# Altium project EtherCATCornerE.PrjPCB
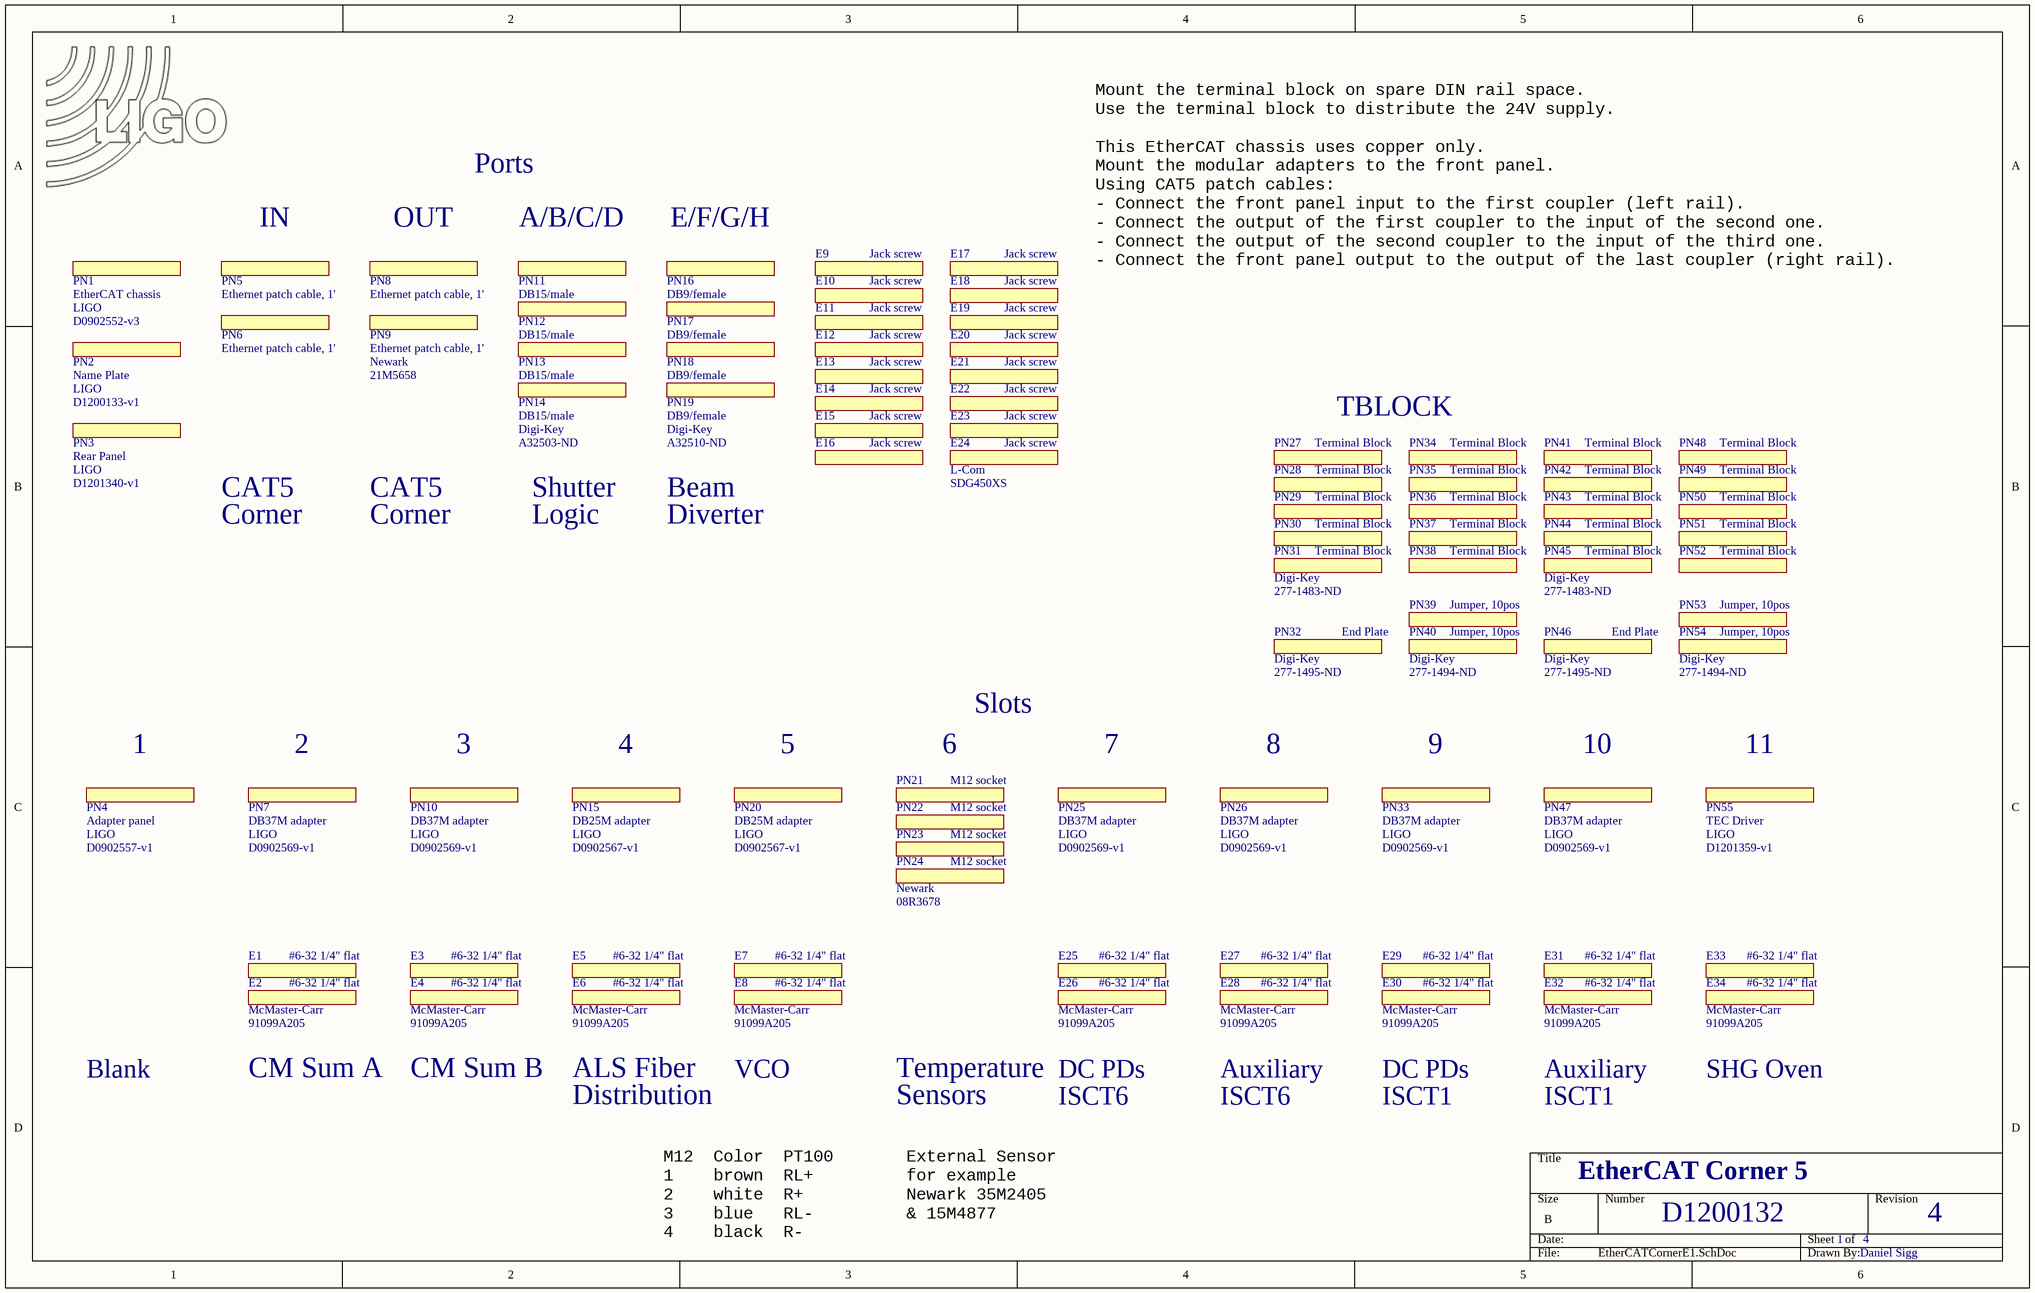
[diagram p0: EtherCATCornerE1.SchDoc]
Title: D1200132
4 sheets, 167 parts. Net scope: global (net labels, ports and power ports of the same name join across sheets).
Sheets:
  EtherCATCornerE1.SchDoc
  EtherCATCornerE2.SchDoc
  EtherCATCornerE3.SchDoc
  EtherCATCornerE4.SchDoc

## Sheet EtherCATCornerE1.SchDoc: D1200132
size B; Engineer: Daniel Sigg; Revision: 3; PageSetup: Record=PageOptions¦CenterHorizontal=True¦CenterVertical=True¦PrintScale=1.12¦XCorrection=1.00¦YCorrection=1.00¦PrintKind=0¦BorderSize=5000000¦LeftOffset=0¦BottomOffset=0¦Orientation=2¦PaperLength=1000¦PaperWidth=1000¦Scale=100¦PaperSource=7¦PrintQuality=-4¦MediaType=1¦DitherType=10¦PaperKind=11 x 17¦PrintScaleMode=1

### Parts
E1  #6-32 1/4" flat  (mechanical)
E2  #6-32 1/4" flat  Part Number: 91099A205  Distributor: McMaster-Carr  (mechanical)
E3  #6-32 1/4" flat  (mechanical)
E4  #6-32 1/4" flat  Part Number: 91099A205  Distributor: McMaster-Carr  (mechanical)
E5  #6-32 1/4" flat  (mechanical)
E6  #6-32 1/4" flat  Part Number: 91099A205  Distributor: McMaster-Carr  (mechanical)
E7  #6-32 1/4" flat  (mechanical)
E8  #6-32 1/4" flat  Part Number: 91099A205  Distributor: McMaster-Carr  (mechanical)
E9  Jack screw  (mechanical)
E10  Jack screw  (mechanical)
E11  Jack screw  (mechanical)
E12  Jack screw  (mechanical)
E13  Jack screw  (mechanical)
E14  Jack screw  (mechanical)
E15  Jack screw  (mechanical)
E16  Jack screw  (mechanical)
E17  Jack screw  (mechanical)
E18  Jack screw  (mechanical)
E19  Jack screw  (mechanical)
E20  Jack screw  (mechanical)
E21  Jack screw  (mechanical)
E22  Jack screw  (mechanical)
E23  Jack screw  (mechanical)
E24  Jack screw  Part Number: SDG450XS  Distributor: L-Com  (mechanical)
E25  #6-32 1/4" flat  (mechanical)
E26  #6-32 1/4" flat  Part Number: 91099A205  Distributor: McMaster-Carr  (mechanical)
E27  #6-32 1/4" flat  (mechanical)
E28  #6-32 1/4" flat  Part Number: 91099A205  Distributor: McMaster-Carr  (mechanical)
E29  #6-32 1/4" flat  (mechanical)
E30  #6-32 1/4" flat  Part Number: 91099A205  Distributor: McMaster-Carr  (mechanical)
E31  #6-32 1/4" flat  (mechanical)
E32  #6-32 1/4" flat  Part Number: 91099A205  Distributor: McMaster-Carr  (mechanical)
E33  #6-32 1/4" flat  (mechanical)
E34  #6-32 1/4" flat  Part Number: 91099A205  Distributor: McMaster-Carr  (mechanical)
LOGO?  LIGO logo  [LIGO_LOGO]  (value not drawn)  (graphical)
PN1  EtherCAT chassis  Part Number: D0902552-v3  Distributor: LIGO  (mechanical)
PN2  Name Plate  Part Number: D1200133-v1  Distributor: LIGO  (mechanical)
PN3  Rear Panel  Part Number: D1201340-v1  Distributor: LIGO  (mechanical)
PN4  Adapter panel  Part Number: D0902557-v1  Distributor: LIGO  (mechanical)
PN5  Ethernet patch cable, 1'  (mechanical)
PN6  Ethernet patch cable, 1'  (mechanical)
PN7  DB37M adapter  Part Number: D0902569-v1  Distributor: LIGO  (mechanical)
PN8  Ethernet patch cable, 1'  (mechanical)
PN9  Ethernet patch cable, 1'  Part Number: 21M5658  Distributor: Newark  (mechanical)
PN10  DB37M adapter  Part Number: D0902569-v1  Distributor: LIGO  (mechanical)
PN11  DB15/male  (mechanical)
PN12  DB15/male  (mechanical)
PN13  DB15/male  (mechanical)
PN14  DB15/male  Part Number: A32503-ND  Distributor: Digi-Key  (mechanical)
PN15  DB25M adapter  Part Number: D0902567-v1  Distributor: LIGO  (mechanical)
PN16  DB9/female  (mechanical)
PN17  DB9/female  (mechanical)
PN18  DB9/female  (mechanical)
PN19  DB9/female  Part Number: A32510-ND  Distributor: Digi-Key  (mechanical)
PN20  DB25M adapter  Part Number: D0902567-v1  Distributor: LIGO  (mechanical)
PN21  M12 socket  (mechanical)
PN22  M12 socket  (mechanical)
PN23  M12 socket  (mechanical)
PN24  M12 socket  Part Number: 08R3678  Distributor: Newark  (mechanical)
PN25  DB37M adapter  Part Number: D0902569-v1  Distributor: LIGO  (mechanical)
PN26  DB37M adapter  Part Number: D0902569-v1  Distributor: LIGO  (mechanical)
PN27  Terminal Block  (mechanical)
PN28  Terminal Block  (mechanical)
PN29  Terminal Block  (mechanical)
PN30  Terminal Block  (mechanical)
PN31  Terminal Block  Part Number: 277-1483-ND  Distributor: Digi-Key  (mechanical)
PN32  End Plate  Part Number: 277-1495-ND  Distributor: Digi-Key  (mechanical)
PN33  DB37M adapter  Part Number: D0902569-v1  Distributor: LIGO  (mechanical)
PN34  Terminal Block  (mechanical)
PN35  Terminal Block  (mechanical)
PN36  Terminal Block  (mechanical)
PN37  Terminal Block  (mechanical)
PN38  Terminal Block  (mechanical)
PN39  Jumper, 10pos  (mechanical)
PN40  Jumper, 10pos  Part Number: 277-1494-ND  Distributor: Digi-Key  (mechanical)
PN41  Terminal Block  (mechanical)
PN42  Terminal Block  (mechanical)
PN43  Terminal Block  (mechanical)
PN44  Terminal Block  (mechanical)
PN45  Terminal Block  Part Number: 277-1483-ND  Distributor: Digi-Key  (mechanical)
PN46  End Plate  Part Number: 277-1495-ND  Distributor: Digi-Key  (mechanical)
PN47  DB37M adapter  Part Number: D0902569-v1  Distributor: LIGO  (mechanical)
PN48  Terminal Block  (mechanical)
PN49  Terminal Block  (mechanical)
PN50  Terminal Block  (mechanical)
PN51  Terminal Block  (mechanical)
PN52  Terminal Block  (mechanical)
PN53  Jumper, 10pos  (mechanical)
PN54  Jumper, 10pos  Part Number: 277-1494-ND  Distributor: Digi-Key  (mechanical)
PN55  TEC Driver  Part Number: D1201359-v1  Distributor: LIGO  (mechanical)

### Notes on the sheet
- (near PN5) IN
- (near PN8) OUT
- Ports
- (near PN11) A/B/C/D
- (near PN16) E/F/G/H
- Mount the terminal block on spare DIN rail space.
  Use the terminal block to distribute the 24V supply.
  This EtherCAT chassis uses copper only.
  Mount the modular adapters to the front panel.
  Using CAT5 patch cables:
  - Connect the front panel input to the first coupler (left rail).
  - Connect the output of the first coupler to the input of the second one.
  - Connect the output of the second coupler to the input of the third one.
  - Connect the front panel output to the output of the last coupler (right rail).
- (near PN34) TBLOCK
- CAT5
- Shutter
- Beam
- Corner
- Logic
- Diverter
- (near PN4) 1
- (near PN7) 2
- (near PN10) 3
- (near PN15) 4
- (near PN20) 5
- 6
- Slots
- (near PN25) 7
- (near PN26) 8
- (near PN33) 9
- (near PN47) 10
- (near PN55) 11
- Blank
- CM Sum A
- CM Sum B
- ALS Fiber
- Distribution
- VCO
- Temperature
- Sensors
- DC PDs
- ISCT6
- Auxiliary
- ISCT1
- SHG Oven
- EtherCAT Corner 5
- M12  Color  PT100
  1    brown  RL+
  2    white  R+
  3    blue   RL-
  4    black  R-
- External Sensor
  for example
  Newark 35M2405
  & 15M4877
- D1200132
- 1
- 4
- Daniel Sigg

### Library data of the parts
E1 E3 E5 E7 E25 E27 E29 E31 E33 = Partlist: #6-32 1/4" flat head screw; Part Number: 91099A205
E2 E4 E6 E8 E26 E28 E30 E32 E34 = Partlist: #6-32 1/4" flat head screw
E9-E23 = Partlist: Jack screw, 45 inch thread; Part Number: SDG450XS
E24 = Partlist: Jack screw, 45 inch thread
LOGO? = LIGO_logo
PN1-PN3 PN7 PN9 PN10 PN14 PN15 PN19 PN20 PN24-PN26 PN33 PN47 = Partlist: Additional part number
PN4 = Partlist: Blank
PN5 PN6 PN8 = Partlist: Additional part number; Part Number: 21M5658
PN11-PN13 = Partlist: Additional part number; Part Number: A32503-ND
PN16-PN18 = Partlist: Additional part number; Part Number: A32510-ND
PN21-PN23 = Partlist: Additional part number; Part Number: 08R3678
PN27-PN30 PN34-PN38 PN41-PN44 PN48-PN52 = Partlist: Part Number: 277-1483-ND
PN31 PN32 PN40 PN45 PN46 PN54 = Partlist
PN39 PN53 = Partlist: Part Number: 277-1494-ND
PN55 = Partlist: TEC Driver PCB

## Sheet EtherCATCornerE2.SchDoc: D1200132
size B
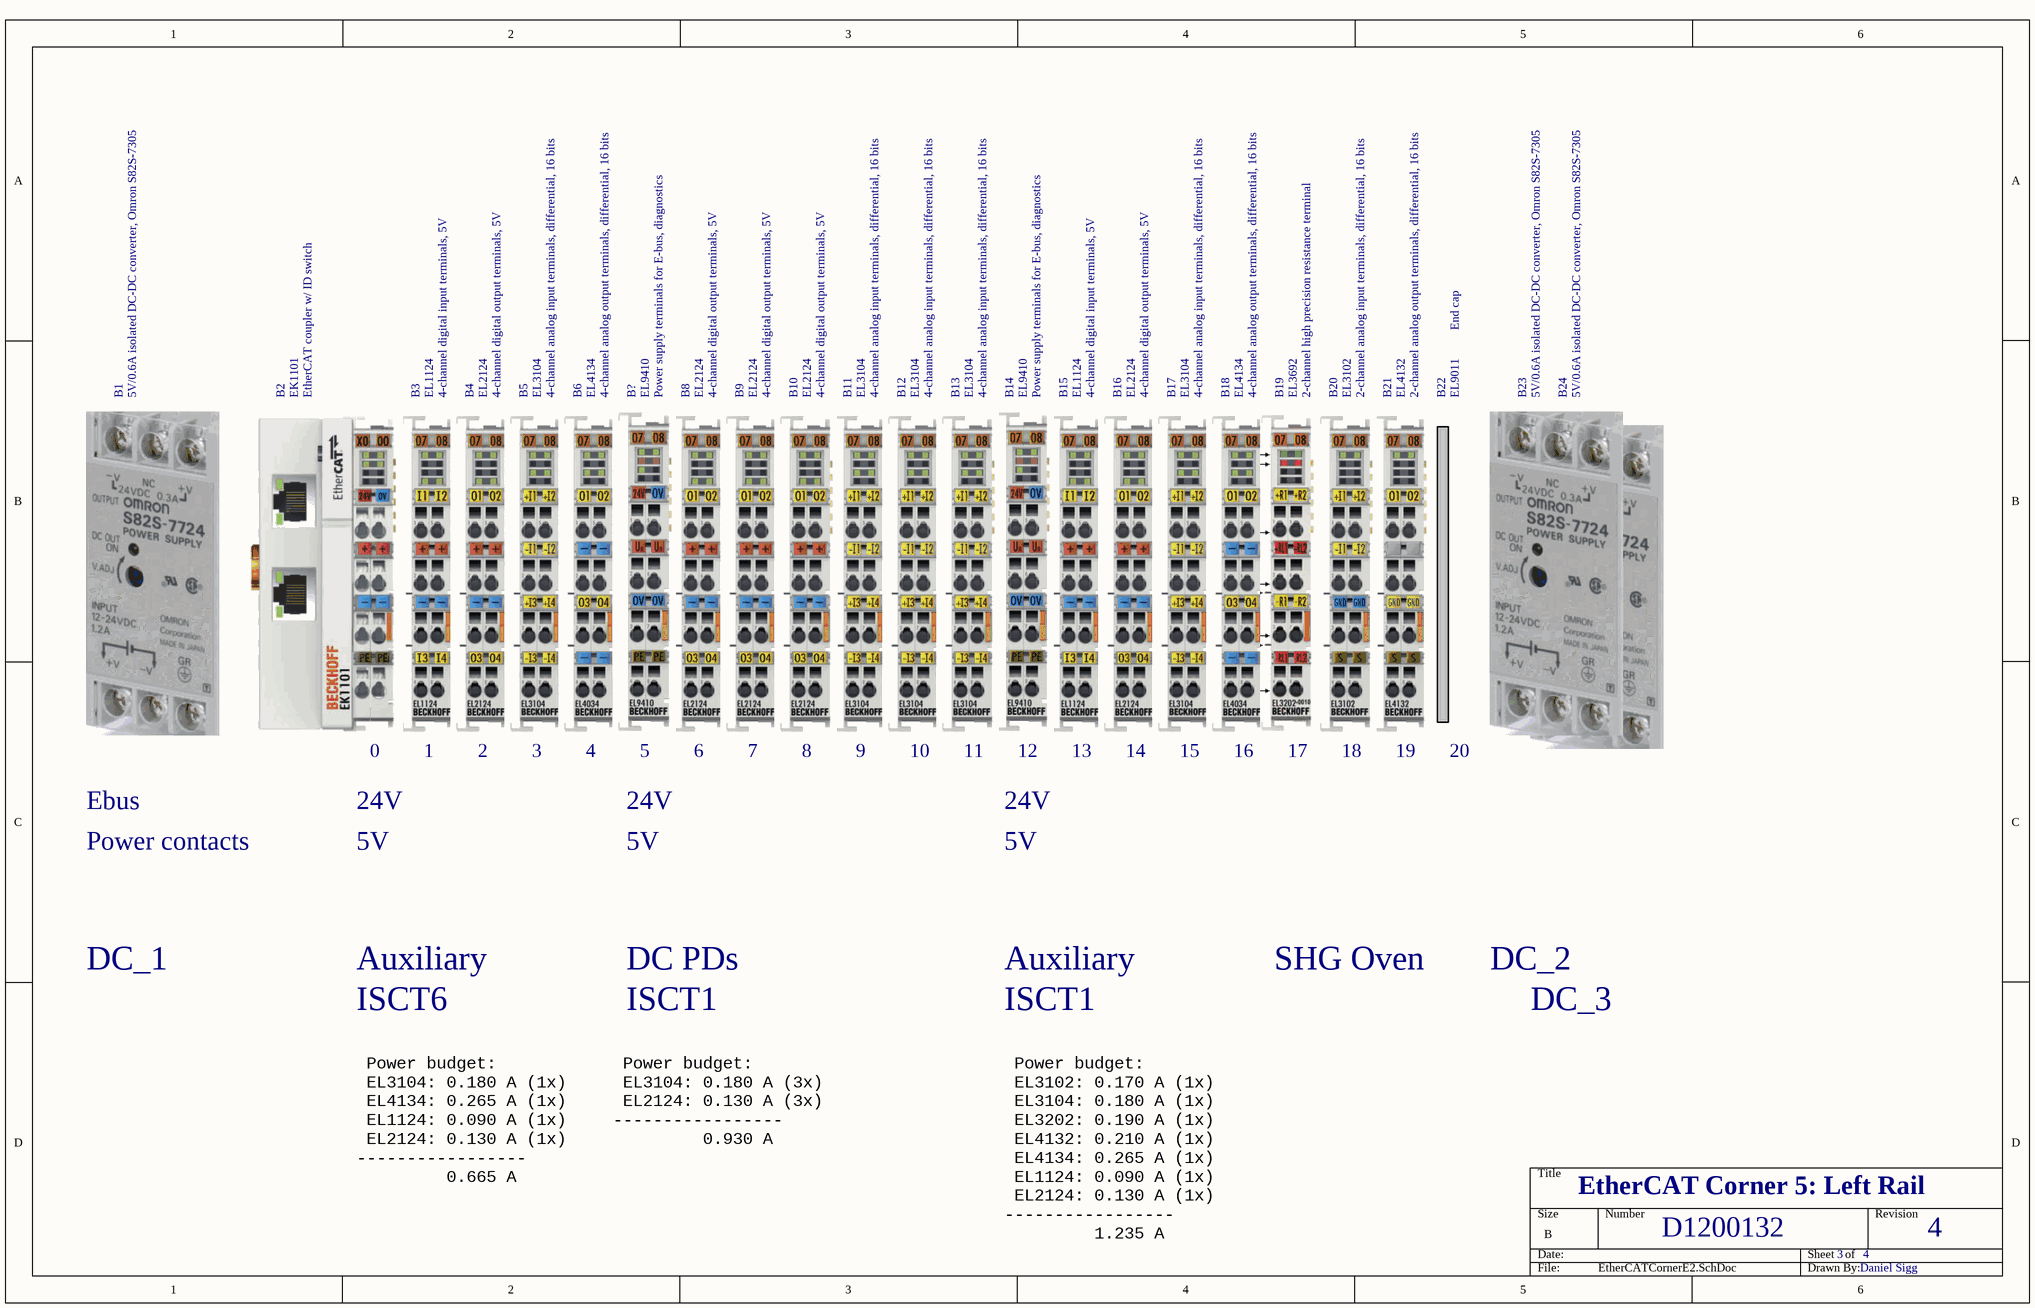
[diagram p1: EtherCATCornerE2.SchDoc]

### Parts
B1  5V/0.6A isolated DC-DC converter, Omron S82S-7305
B2  EtherCAT coupler w/ ID switch
B3  4-channel digital input terminals, 5V
B4  4-channel digital output terminals, 5V
B5  4-channel analog input terminals, differential, 16 bits
B6  4-channel analog output terminals, differential, 16 bits
B8  4-channel digital output terminals, 5V
B9  4-channel digital output terminals, 5V
B10  4-channel digital output terminals, 5V
B11  4-channel analog input terminals, differential, 16 bits
B12  4-channel analog input terminals, differential, 16 bits
B13  4-channel analog input terminals, differential, 16 bits
B14  Power supply terminals for E-bus, diagnostics
B15  4-channel digital input terminals, 5V
B16  4-channel digital output terminals, 5V
B17  4-channel analog input terminals, differential, 16 bits
B18  4-channel analog output terminals, differential, 16 bits
B19  2-channel high precision resistance terminal  Part Number: EL3692
B20  2-channel analog input terminals, differential, 16 bits
B21  2-channel analog output terminals, differential, 16 bits
B22  End cap
B23  5V/0.6A isolated DC-DC converter, Omron S82S-7305
B24  5V/0.6A isolated DC-DC converter, Omron S82S-7305
B?  Power supply terminals for E-bus, diagnostics

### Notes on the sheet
- (near B3) 0
- 1
- 2
- 3
- 4
- 5
- 6
- 7
- 8
- 9
- (near B13) 10
- (near B14) 11
- (near B15) 12
- (near B16) 13
- (near B17) 14
- (near B18) 15
- (near B19) 16
- (near B20) 17
- (near B21) 18
- (near B22) 19
- 20
- (near B1) Ebus
- Power contacts
- 24V
- 5V
- DC_1
- Auxiliary
- DC PDs
- SHG Oven
- DC_2
- ISCT6
- ISCT1
- DC_3
- EtherCAT Corner 5: Left Rail
- Power budget:
  EL3104: 0.180 A (1x)
  EL4134: 0.265 A (1x)
  EL1124: 0.090 A (1x)
  EL2124: 0.130 A (1x)
  -----------------
  0.665 A
- Power budget:
  EL3104: 0.180 A (3x)
  EL2124: 0.130 A (3x)
  -----------------
  0.930 A
- Power budget:
  EL3102: 0.170 A (1x)
  EL3104: 0.180 A (1x)
  EL3202: 0.190 A (1x)
  EL4132: 0.210 A (1x)
  EL4134: 0.265 A (1x)
  EL1124: 0.090 A (1x)
  EL2124: 0.130 A (1x)
  -----------------
  1.235 A
- D1200132
- Daniel Sigg

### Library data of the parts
B1 B23 B24 = S82S-7305: Part Number: 27C5226
B2 = EK1101: Beckhoff EtherCAT coupler w/ ID switch
B3 B15 = EL1124
B4 B8-B10 B16 = EL2124
B5 B11-B13 B17 = EL3104
B6 B18 = EL4134
B14 B? = EL9410
B19 = EL3202-0010: 2-channel high precision input terminal PT100 (RTD) for 2- or 3-wire connection
B20 = EL3102
B21 = EL4132
B22 = EL9011

## Sheet EtherCATCornerE3.SchDoc: D1200132
size B
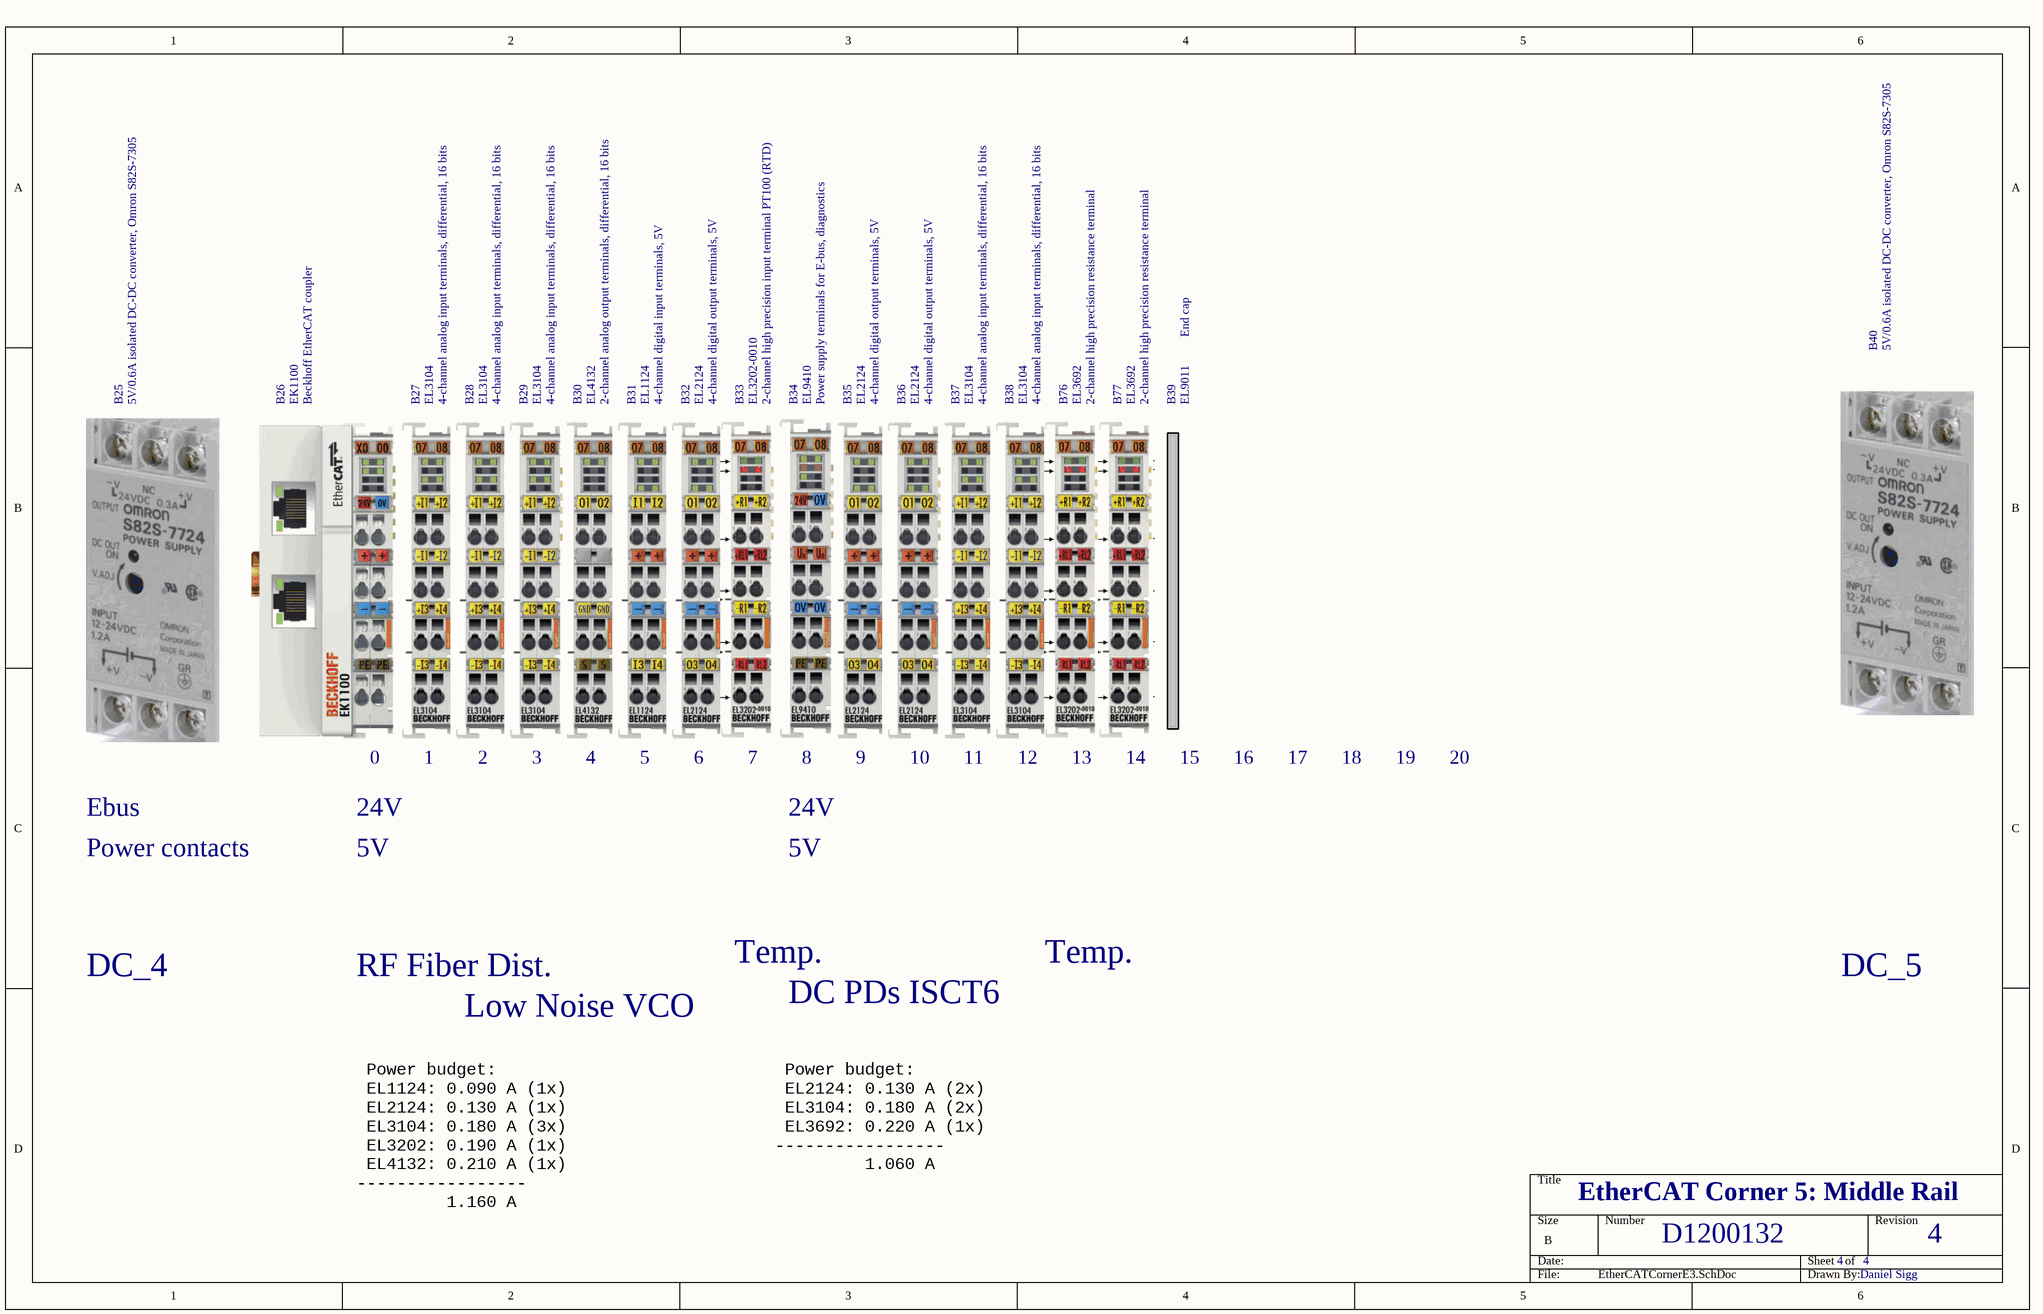
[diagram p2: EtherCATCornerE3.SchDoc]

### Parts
B25  5V/0.6A isolated DC-DC converter, Omron S82S-7305
B26  Beckhoff EtherCAT coupler
B27  4-channel analog input terminals, differential, 16 bits
B28  4-channel analog input terminals, differential, 16 bits
B29  4-channel analog input terminals, differential, 16 bits
B30  2-channel analog output terminals, differential, 16 bits
B31  4-channel digital input terminals, 5V
B32  4-channel digital output terminals, 5V
B33  2-channel high precision input terminal PT100 (RTD)
B34  Power supply terminals for E-bus, diagnostics
B35  4-channel digital output terminals, 5V
B36  4-channel digital output terminals, 5V
B37  4-channel analog input terminals, differential, 16 bits
B38  4-channel analog input terminals, differential, 16 bits
B39  End cap
B40  5V/0.6A isolated DC-DC converter, Omron S82S-7305
B76  2-channel high precision resistance terminal  Part Number: EL3692
B77  2-channel high precision resistance terminal  Part Number: EL3692

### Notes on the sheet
- (near B27) 0
- 1
- 2
- 3
- 4
- 5
- 6
- 7
- 8
- 9
- (near B37) 10
- (near B38) 11
- (near B76) 12
- (near B77) 13
- (near B39) 14
- (near B39) 15
- 16
- 17
- 18
- 19
- 20
- (near B25) Ebus
- Power contacts
- 24V
- 5V
- DC_4
- RF Fiber Dist.
- Temp.
- DC_5
- Low Noise VCO
- DC PDs ISCT6
- EtherCAT Corner 5: Middle Rail
- Power budget:
  EL1124: 0.090 A (1x)
  EL2124: 0.130 A (1x)
  EL3104: 0.180 A (3x)
  EL3202: 0.190 A (1x)
  EL4132: 0.210 A (1x)
  -----------------
  1.160 A
- Power budget:
  EL2124: 0.130 A (2x)
  EL3104: 0.180 A (2x)
  EL3692: 0.220 A (1x)
  -----------------
  1.060 A
- D1200132
- Daniel Sigg

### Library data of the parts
B25 B40 = S82S-7305: Part Number: 27C5226
B26 = EK1100
B27-B29 B37 B38 = EL3104
B30 = EL4132
B31 = EL1124
B32 B35 B36 = EL2124
B33 B76 B77 = EL3202-0010: as B19 on sheet EtherCATCornerE2
B34 = EL9410
B39 = EL9011

## Sheet EtherCATCornerE4.SchDoc: D1200132
size B
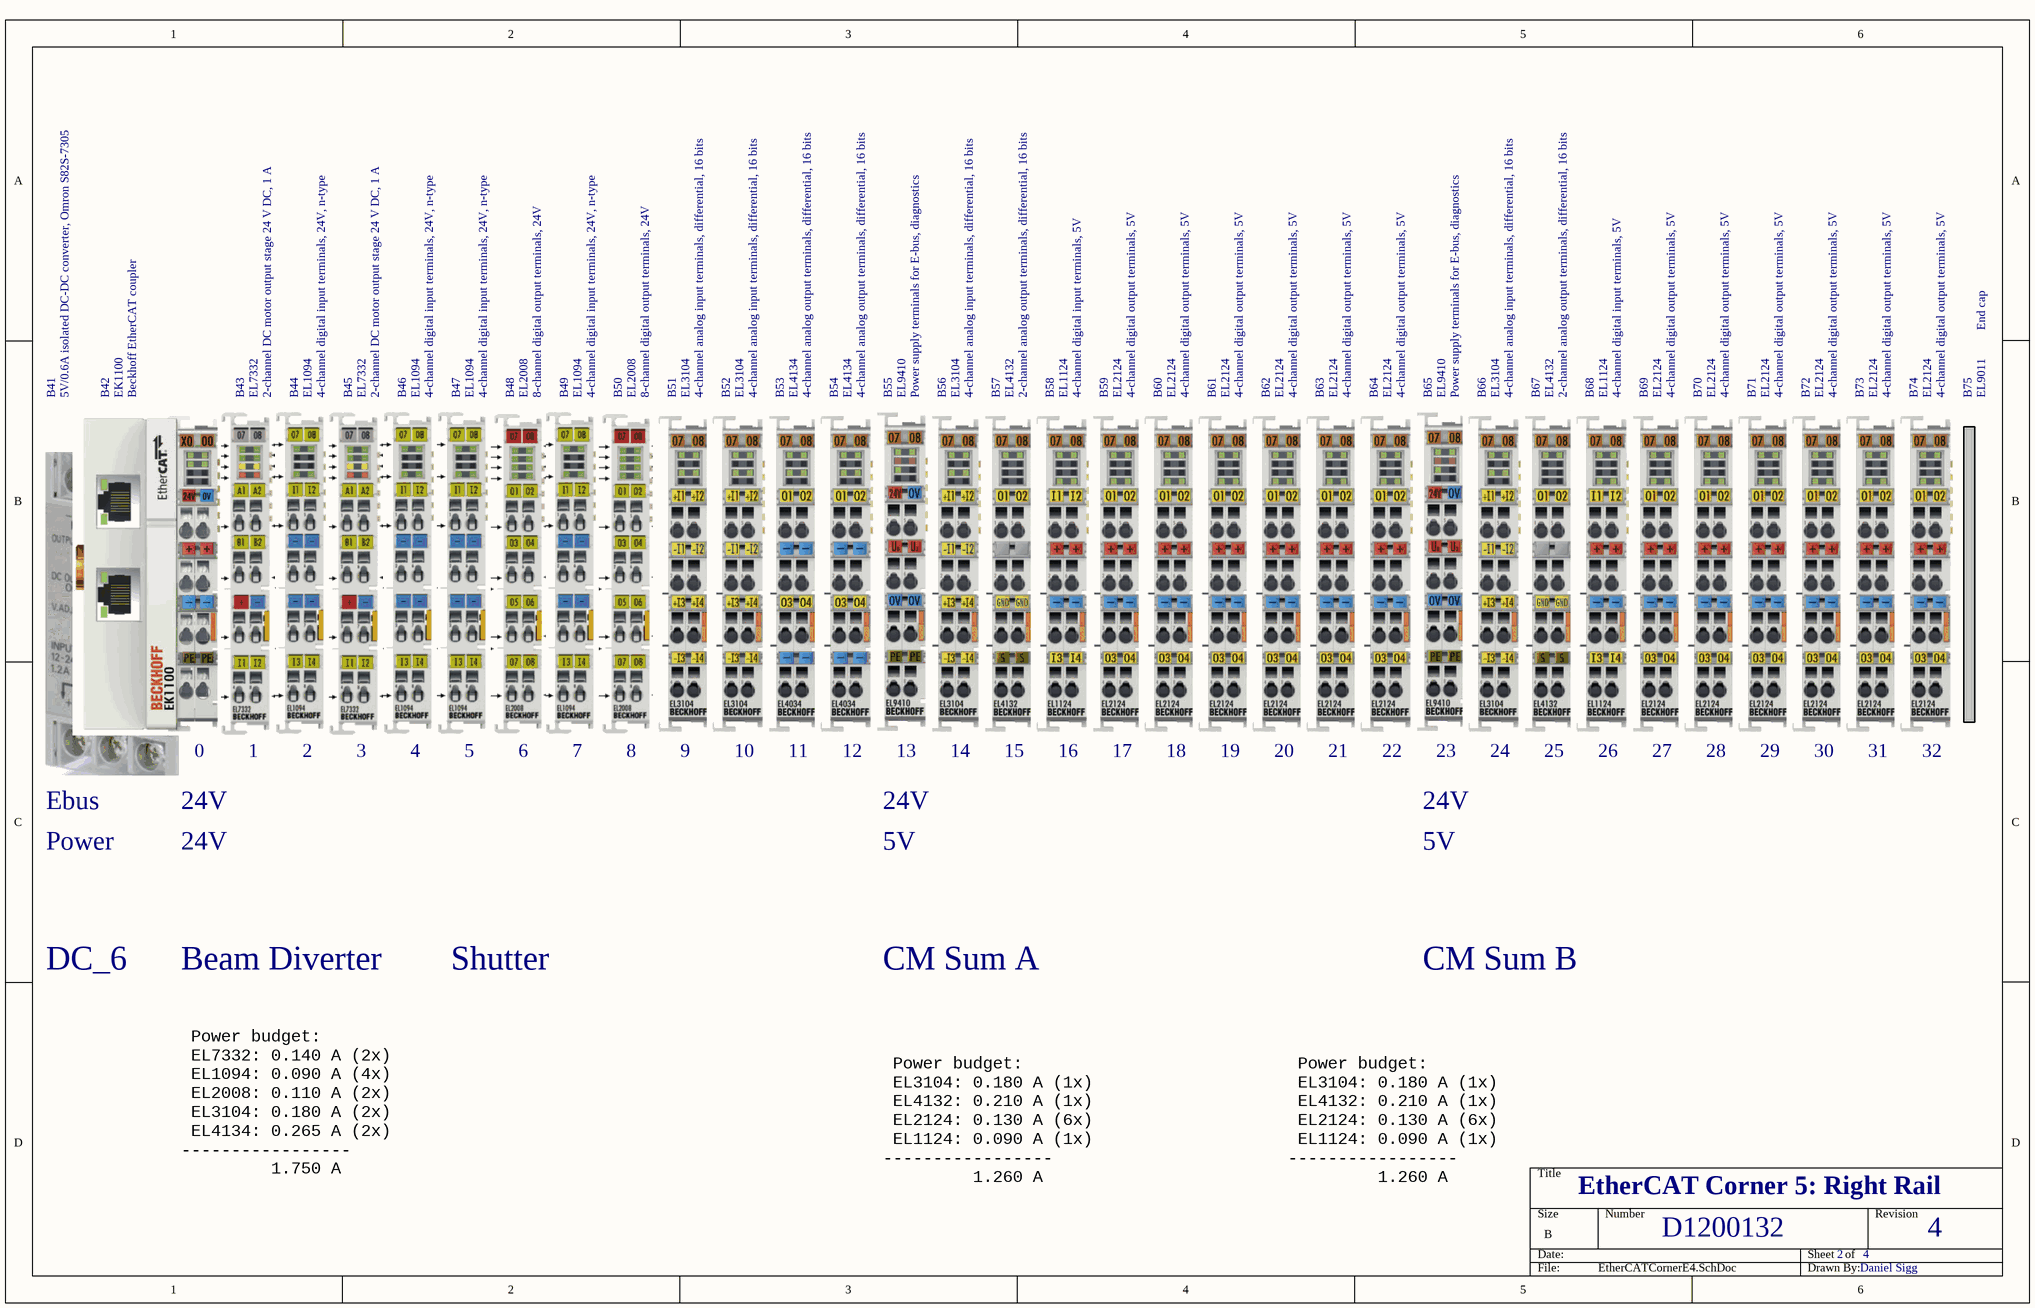
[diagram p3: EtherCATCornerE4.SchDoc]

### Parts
B41  5V/0.6A isolated DC-DC converter, Omron S82S-7305
B42  Beckhoff EtherCAT coupler
B43  2-channel DC motor output stage 24 V DC, 1 A
B44  4-channel digital input terminals, 24V, n-type
B45  2-channel DC motor output stage 24 V DC, 1 A
B46  4-channel digital input terminals, 24V, n-type
B47  4-channel digital input terminals, 24V, n-type
B48  8-channel digital output terminals, 24V
B49  4-channel digital input terminals, 24V, n-type
B50  8-channel digital output terminals, 24V
B51  4-channel analog input terminals, differential, 16 bits
B52  4-channel analog input terminals, differential, 16 bits
B53  4-channel analog output terminals, differential, 16 bits
B54  4-channel analog output terminals, differential, 16 bits
B55  Power supply terminals for E-bus, diagnostics
B56  4-channel analog input terminals, differential, 16 bits
B57  2-channel analog output terminals, differential, 16 bits
B58  4-channel digital input terminals, 5V
B59  4-channel digital output terminals, 5V
B60  4-channel digital output terminals, 5V
B61  4-channel digital output terminals, 5V
B62  4-channel digital output terminals, 5V
B63  4-channel digital output terminals, 5V
B64  4-channel digital output terminals, 5V
B65  Power supply terminals for E-bus, diagnostics
B66  4-channel analog input terminals, differential, 16 bits
B67  2-channel analog output terminals, differential, 16 bits
B68  4-channel digital input terminals, 5V
B69  4-channel digital output terminals, 5V
B70  4-channel digital output terminals, 5V
B71  4-channel digital output terminals, 5V
B72  4-channel digital output terminals, 5V
B73  4-channel digital output terminals, 5V
B74  4-channel digital output terminals, 5V
B75  End cap

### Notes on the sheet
- (near B43) 0
- 1
- 2
- 3
- 4
- 5
- 6
- 7
- 8
- 9
- (near B53) 10
- (near B54) 11
- (near B55) 12
- (near B56) 13
- (near B57) 14
- (near B58) 15
- (near B59) 16
- (near B60) 17
- (near B61) 18
- (near B62) 19
- (near B63) 20
- (near B64) 21
- (near B65) 22
- (near B66) 23
- (near B67) 24
- (near B68) 25
- (near B69) 26
- (near B70) 27
- (near B71) 28
- (near B72) 29
- (near B73) 30
- (near B74) 31
- (near B75) 32
- (near B41) Ebus
- (near B41) Power
- 24V
- 5V
- DC_6
- Beam Diverter
- Shutter
- CM Sum A
- CM Sum B
- Power budget:
  EL7332: 0.140 A (2x)
  EL1094: 0.090 A (4x)
  EL2008: 0.110 A (2x)
  EL3104: 0.180 A (2x)
  EL4134: 0.265 A (2x)
  -----------------
  1.750 A
- EtherCAT Corner 5: Right Rail
- Power budget:
  EL3104: 0.180 A (1x)
  EL4132: 0.210 A (1x)
  EL2124: 0.130 A (6x)
  EL1124: 0.090 A (1x)
  -----------------
  1.260 A
- D1200132
- Daniel Sigg

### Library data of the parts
B41 = S82S-7305: Part Number: 27C5226
B42 = EK1100
B43 B45 = EL7332
B44 B46 B47 B49 = EL1094: 4-channel digital input terminal, 24V, 10 µs, n-type
B48 B50 = EL2008: 8-channel digital output terminal, 24V
B51 B52 B56 B66 = EL3104
B53 B54 = EL4134
B55 B65 = EL9410
B57 B67 = EL4132
B58 B68 = EL1124
B59-B64 B69-B74 = EL2124
B75 = EL9011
